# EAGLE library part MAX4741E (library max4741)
Dual SPST Analog Switches on SOT23-8 Package
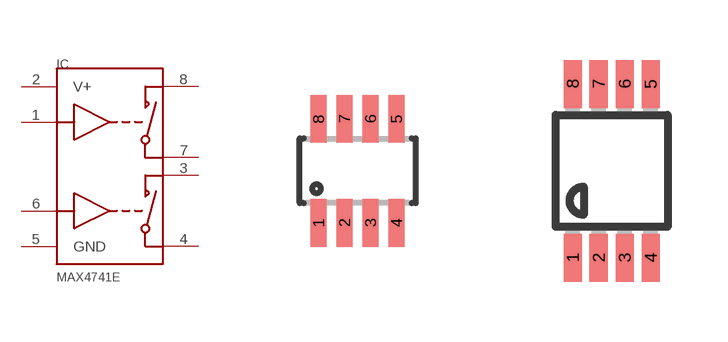
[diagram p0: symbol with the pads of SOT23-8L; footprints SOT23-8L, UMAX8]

Designator prefix IC

## MAX4741EKA  [SOT23-8L]
1  IN1  in
2  V+  pwr
3  NO2  pas
4  COM2  pas
5  GND  pwr
6  IN2  in
7  COM1  pas
8  NO1  pas

## MAX4741EUA  [UMAX8]
1  NO1  pas
2  COM1  pas
3  IN2  in
4  GND  pwr
5  NO2  pas
6  COM2  pas
7  IN1  in
8  V+  pwr

## Footprint SOT23-8L (pad centres in mm)
Pitch=0.65mm, 8P
smd 0.4 x 1.2: 1 -0.95,-1.3; 2 -0.3,-1.3; 3 0.35,-1.3; 4 1,-1.3; 5 1,1.3; 6 0.35,1.3; 7 -0.3,1.3; 8 -0.95,1.3

## Footprint UMAX8 (pad centres in mm)
micro MAX Package
smd 0.45 x 1.2: 1 -0.975,-2.175; 2 -0.325,-2.175; 3 0.325,-2.175; 4 0.975,-2.175; 5 0.975,2.175; 6 0.325,2.175; 7 -0.325,2.175; 8 -0.975,2.175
